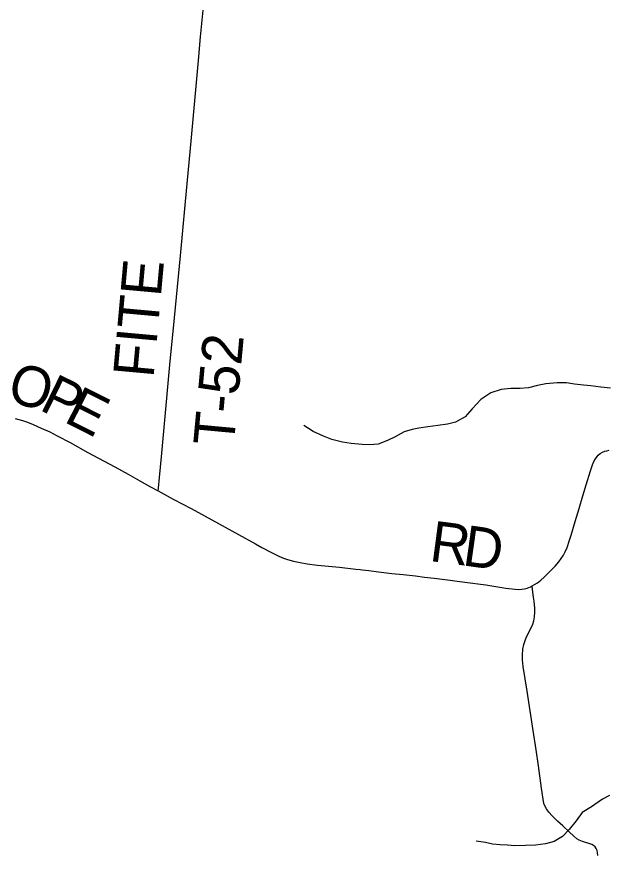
# Model space of a CAD drawing. Extents: x 1451455 to 1749751, y 218250 to 574981.
# Drawn here: x 1559243 to 1563625, y 349860 to 356052 of the extents above; entities that cross this region are included whole.
import ezdxf

# ---------------------------------------------------------------- set-up
doc = ezdxf.new("R2010")
doc.units = 0
for name, color, linetype in [('GM_X_County_Road', 7, 'Continuous'), ('GM_X_County_Road_Text', 7, 'Continuous'), ('GM_X_Minor_River', 7, 'Continuous'), ('GM_X_Township_Road', 7, 'Continuous'), ('GM_X_Township_Road_Text', 7, 'Continuous')]:
    doc.layers.add(name, color=color, linetype=linetype)

msp = doc.modelspace()

# ---------------------------------------------------------------- linework, layer by layer
at = {"layer": 'GM_X_County_Road'}
for points in [[(1559230.7, 353081.4), (1559284.2, 353066.9), (1559321.2, 353054.3), (1559363.7, 353037.4), (1559423.8, 353011.5), (1559486.3, 352982.8), (1559541.9, 352955), (1559637.4, 352904.2), (1559769.7, 352831.7), (1559968.6, 352723.6), (1560066.3, 352670), (1560117.8, 352641.4), (1560152, 352622.1), (1560232.2, 352577.4), (1560287.8, 352547.3)], [(1563053.6, 351843.9), (1563072.5, 351853.7), (1563095.1, 351868), (1563118.8, 351886.1), (1563143.5, 351908.2), (1563183.2, 351947.5), (1563224, 351990.2), (1563251.9, 352022.7), (1563269.8, 352046.5), (1563285.9, 352071.8), (1563298.2, 352095.4), (1563312.2, 352128.9), (1563330.7, 352181.5), (1563342.5, 352219), (1563373, 352319.3), (1563402.6, 352416.5), (1563430.1, 352511), (1563439, 352542.5), (1563450.5, 352583.6), (1563465, 352630.6), (1563473, 352655.5), (1563487.5, 352702.5), (1563500.4, 352739.3), (1563510.8, 352763), (1563521.8, 352782.6), (1563534.8, 352800.6), (1563543.3, 352809.8), (1563557.5, 352822.1), (1563573.6, 352832), (1563591, 352839.4), (1563606.2, 352843.8), (1563625.1, 352847)], [(1560287.8, 352547.3), (1560399.5, 352486.7), (1560532.7, 352416), (1560636.1, 352359.1), (1560883.4, 352223.3), (1561007.5, 352156.4), (1561055.9, 352128.8), (1561125.6, 352092.2), (1561181.2, 352064.6), (1561214.6, 352050.2), (1561246, 352039.7), (1561290.6, 352027.5), (1561338.9, 352016.9), (1561390.8, 352008.1), (1561465.9, 351998.4), (1561629.2, 351982.5), (1561749.6, 351968.8), (1561782.1, 351965), (1561798.3, 351962.9), (1561847.1, 351957.1), (1561918.7, 351948.5), (1562016.5, 351937), (1562101.3, 351928.5), (1562192.4, 351917.5), (1562257.4, 351909.5), (1562329, 351901), (1562448.8, 351886.6), (1562500.6, 351880), (1562595, 351868), (1562673, 351858.3), (1562711.8, 351852.5), (1562860.8, 351828.4), (1562929.2, 351820.1), (1562955.8, 351818.8), (1562979.1, 351819.9), (1562998.9, 351823), (1563018.3, 351828.4), (1563043, 351838.4), (1563053.6, 351843.9)], [(1563540.9, 349850.6), (1563538.8, 349872.8), (1563535, 349887.9), (1563528.5, 349901.8), (1563519.5, 349914.2), (1563508.2, 349924.5), (1563495, 349932.4), (1563474.3, 349940.3), (1563427.2, 349954.5), (1563402.6, 349964.8), (1563385.3, 349975.1), (1563361.6, 349993.7), (1563328.4, 350025.6), (1563280.2, 350069.8), (1563241.7, 350105.3), (1563201.8, 350144.1), (1563177.2, 350171), (1563159.6, 350195.2), (1563149.9, 350212.8), (1563141.8, 350235), (1563134.7, 350267.5), (1563122.7, 350348.9), (1563101.9, 350514.9), (1563084.5, 350631.5), (1563062.9, 350774.2), (1563016.5, 351065.8), (1562988.1, 351247.4), (1562982.8, 351296.6), (1562982.7, 351333.2), (1562986.4, 351376.1), (1562993.1, 351412), (1563001.8, 351440.7), (1563013.5, 351468.3), (1563045, 351529.5), (1563059.3, 351562), (1563066.9, 351586.1), (1563072.3, 351614.4), (1563075.2, 351649.8), (1563075.1, 351678.8), (1563069.7, 351730.6), (1563065, 351762.2), (1563057.2, 351818.2), (1563053.6, 351843.9)]]:
    msp.add_lwpolyline(points, dxfattribs=at)
at = {"layer": 'GM_X_Minor_River'}
for points in [[(1563633, 353306.7), (1563563, 353313.7), (1563489, 353322.9), (1563433, 353327.7), (1563367, 353336.7), (1563309, 353345.6), (1563238.9, 353346.6), (1563156.6, 353337.8), (1563094.3, 353324.7), (1563027.9, 353309.6), (1562965.7, 353304.5), (1562895.6, 353303.6), (1562825.3, 353296.6), (1562748.8, 353271.7), (1562675.8, 353222.6), (1562610.6, 353153.4), (1562559.5, 353094), (1562488.7, 353055), (1562428.3, 353039.8), (1562356.1, 353030.9), (1562283.7, 353019.9), (1562217.5, 353010.9), (1562167.2, 353001.6), (1562108.8, 352984.4), (1562042.1, 352947.3), (1561985.5, 352920), (1561914.9, 352893), (1561850.7, 352887.9), (1561796.6, 352888.7), (1561716.6, 352895.9), (1561652.7, 352906.9), (1561572.8, 352926.1), (1561511.1, 352951), (1561435.5, 352986.2), (1561366.1, 353031.3)], [(1563626.8, 350295.7), (1563574.3, 350268.4), (1563493.2, 350211.5), (1563424.3, 350168.4), (1563379.2, 350106.9), (1563328.1, 350043.5), (1563279.1, 349992.2), (1563216.4, 349955), (1563154, 349937.9), (1563079.7, 349927), (1563005.6, 349924.1), (1562925.4, 349923.3), (1562871.4, 349928.1), (1562817.4, 349931), (1562761.4, 349935.8), (1562709.4, 349946.6), (1562641.5, 349957.6)]]:
    msp.add_lwpolyline(points, dxfattribs=at)
at = {"layer": 'GM_X_Township_Road'}
msp.add_lwpolyline([(1560287.8, 352547.3), (1560290, 352567.4), (1560298.3, 352646), (1560313.3, 352798), (1560335.4, 353043), (1560375.2, 353477.5), (1560409, 353826.9), (1560453.1, 354284.1), (1560487.8, 354659.8), (1560534.8, 355159.5), (1560588, 355727.9), (1560602.8, 355904.4), (1560621.2, 356100.2)], dxfattribs=at)

# ---------------------------------------------------------------- texts
at = {"layer": 'GM_X_County_Road_Text'}
for s, rotation, p in [('O', 344.81469, (1559161.1, 353213.2)), ('P', 333.98213, (1559401.9, 353149.3)), ('E', 333.23275, (1559582.9, 353061)), ('R', 352.47487, (1562288.1, 352029.8)), ('D', 351.97242, (1562531.7, 351997.6))]:
    msp.add_text(s, height=300, rotation=rotation, dxfattribs=at).set_placement(p)
at = {"layer": 'GM_X_Township_Road_Text'}
for s, rotation, p in [('FITE', 84.80685, (1560253.5, 353377.5)), ('T-52', 84.7201, (1560846.6, 352871))]:
    msp.add_text(s, height=300, rotation=rotation, dxfattribs=at).set_placement(p)

doc.saveas('drawing.dxf')
